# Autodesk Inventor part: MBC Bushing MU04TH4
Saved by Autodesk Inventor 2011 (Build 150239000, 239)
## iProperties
Created: 2011-01
Part Number: MBC Bushing MU04TH4
Document SubType Name: Modeling
Designer: dfranz
Density: 1 g/cm^3
Author: dfranz
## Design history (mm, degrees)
feature "Base1"
node "MBC Bushing MU04TH4"
